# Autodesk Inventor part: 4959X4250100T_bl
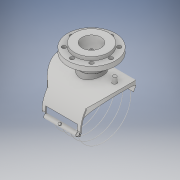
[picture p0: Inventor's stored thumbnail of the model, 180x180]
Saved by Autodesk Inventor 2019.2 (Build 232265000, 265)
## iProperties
Created: 2020-06
Part Number: 4959X4250100T_bl
Material: Generic
Description: Plasson Flanged Branch Saddle 250x100
Document SubType Name: Modeling
Designer: KIM
Density: 1 g/cm^3
Appearance: Default
Author: KIM
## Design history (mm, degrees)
derived "4959X4.ipt"
feature "Solid1::4959X4.ipt" dims "ScaleForDerivedMember" = 10
feature "Solid2::4959X4.ipt" dims "ScaleForDerivedMember" = 10
tag "TaggingFeature1"
body "Solid1"
body "Solid2"
other parameters: "d0" = 295 [user parameter], "d7" = 87 [user parameter], "d10" = 0.5 [user parameter], "d11" = 1 [user parameter], "d13" = 16 [user parameter], "d14" = 8 [user parameter], "d16" = 10 deg [user parameter], "d17" = 10 deg [user parameter], "d19" = 0 [user parameter], "d23" = 0 [user parameter], "d26" = 0 [user parameter], "d27" = 177 [user parameter], "d28" = 0 [user parameter], "d29" = 147.5 [user parameter], "d30" = 0 [user parameter], "d31" = 1 [user parameter], "d32" = 1 [user parameter], "d33" = 19.2 [user parameter], "d34" = 9.6 [user parameter], "d35" = 45 deg [user parameter], "d36" = 147.5 [user parameter], "d37" = 0 [user parameter], "d38" = 5 [user parameter], "d39" = 85 deg [user parameter], "d41" = 16 [user parameter], "d42" = 107.27273 [user parameter], "d49" = 3 [user parameter], "d50" = 6 [user parameter], "d51" = 5 [user parameter], "d54" = 0 [user parameter], "d57" = 35 deg [user parameter], "d60" = 18.4375 [user parameter], "d61" = 1 [user parameter], "d62" = 90 deg [user parameter], "d63" = 2 [user parameter], "d64" = 0 [user parameter], "d65" = 0 [user parameter], "d68" = 36.875 [user parameter], "d70" = 0.57711 [user parameter], "d71" = 10 deg [user parameter], "d73" = 5.25 [user parameter], "d75" = 22 [user parameter], "d77" = 89.25 [user parameter], "d78" = 105 [user parameter], "d79" = 158 [user parameter], "d80" = 1 [user parameter], "d81" = 104.4 [user parameter], "d82" = 121.8 [user parameter], "d83" = 1 [user parameter], "d84" = 16.5 [user parameter], "d87" = 18 [user parameter], "d95" = 360 deg [user parameter], "d_h" = 158 [user parameter], "L" = 295 [user parameter], "LS" = 105 [user parameter], "Dt" = 16 [user parameter], "di" = 87 [user parameter], "s_" = 18 [user parameter], "t" = 22 [user parameter], "d72" = 15 [user parameter]
